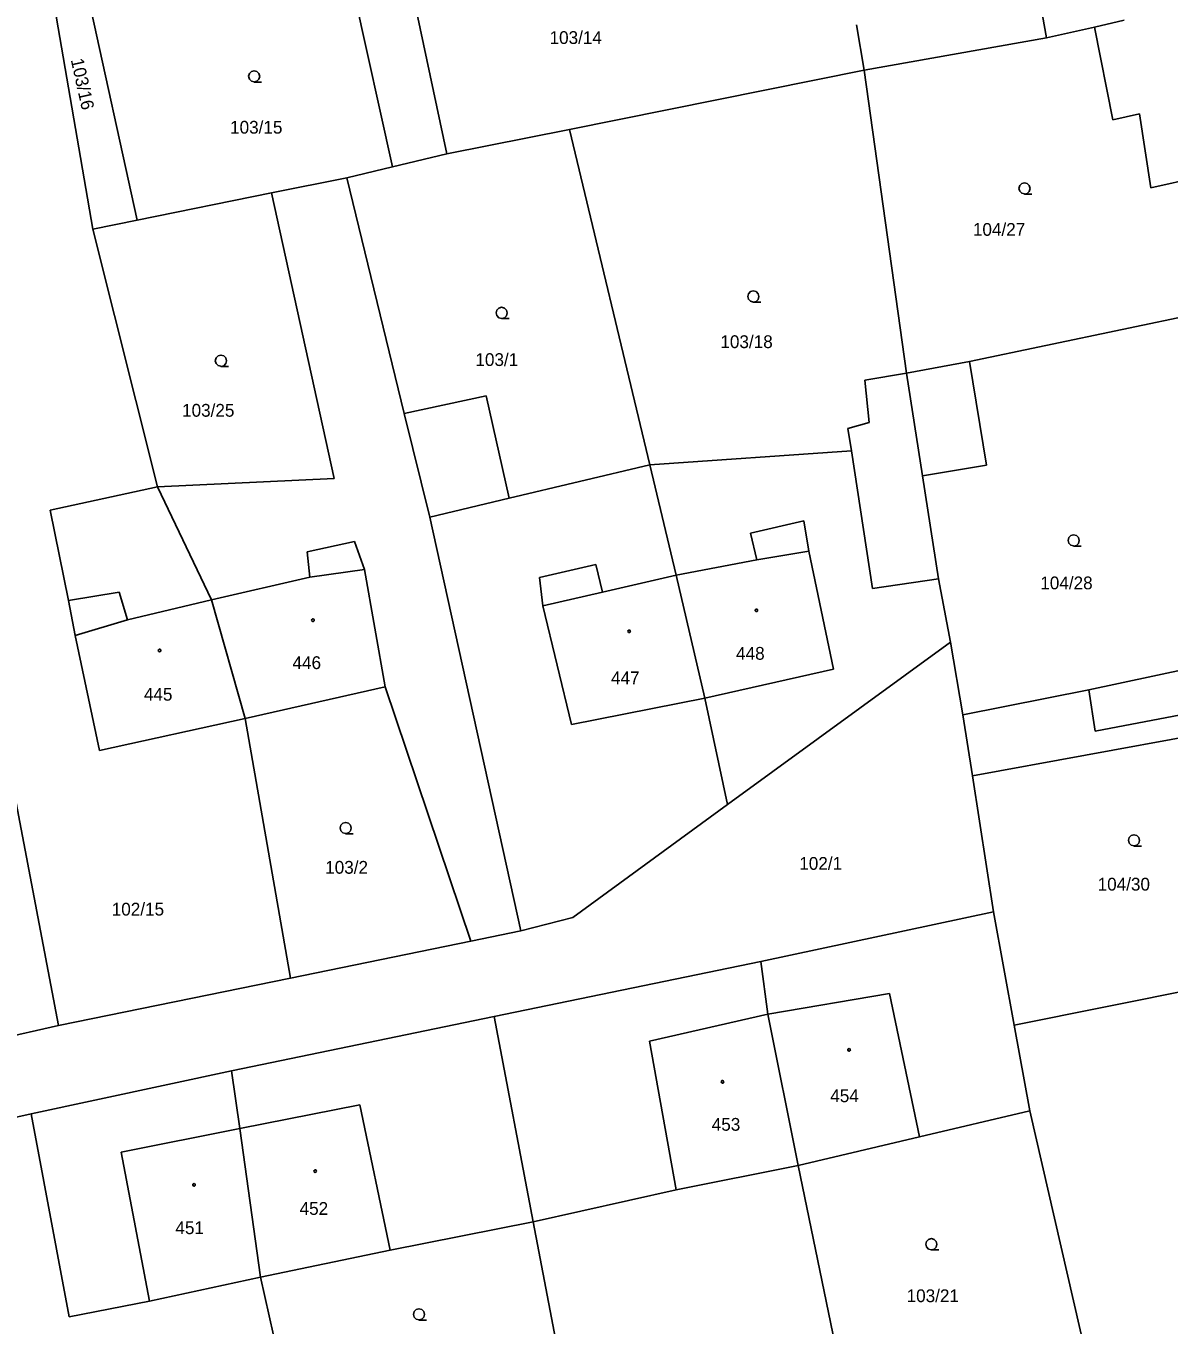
# Model space of a CAD drawing. Extents: x -757994 to -755874, y -1047691 to -1046119.
# Drawn here: x -756795.4 to -756719.4, y -1047241.1 to -1047154.8 of the extents above; entities that cross this region are included whole.
import ezdxf

# ---------------------------------------------------------------- set-up
doc = ezdxf.new("R2010")
doc.units = 0
doc.layers.add('katastrální mapa', color=7, linetype='Continuous')

msp = doc.modelspace()

# ---------------------------------------------------------------- linework, layer by layer
at = {"layer": 'katastrální mapa'}
for p, q in [((-756772.63, -1047138.82), (-756767.41, -1047163.3)), ((-756787.99, -1047167.7), (-756792.24, -1047148.27)), ((-756774.17, -1047149.9), (-756771.02, -1047164.16)), ((-756793.93, -1047150.88), (-756790.93, -1047168.29)), ((-756727.57, -1047155.59), (-756728.16, -1047152.37)), ((-756740.2, -1047154.72), (-756739.68, -1047157.74)), ((-756727.57, -1047155.59), (-756724.39, -1047154.87)), ((-756722.42, -1047154.41), (-756724.39, -1047154.87)), ((-756724.39, -1047154.87), (-756723.16, -1047161.03)), ((-756739.68, -1047157.74), (-756727.57, -1047155.59)), ((-756759.27, -1047161.67), (-756739.68, -1047157.74)), ((-756739.68, -1047157.74), (-756736.87, -1047177.86)), ((-756723.16, -1047161.03), (-756721.39, -1047160.64)), ((-756721.39, -1047160.64), (-756720.64, -1047165.55)), ((-756767.41, -1047163.3), (-756759.27, -1047161.67)), ((-756759.27, -1047161.67), (-756753.93, -1047183.96)), ((-756767.41, -1047163.3), (-756771.02, -1047164.16)), ((-756720.64, -1047165.55), (-756711.7, -1047163.55)), ((-756771.02, -1047164.16), (-756774.06, -1047164.88)), ((-756774.06, -1047164.88), (-756779.07, -1047165.89)), ((-756774.06, -1047164.88), (-756770.25, -1047180.54)), ((-756779.07, -1047165.89), (-756787.99, -1047167.7)), ((-756779.07, -1047165.89), (-756774.89, -1047184.86)), ((-756787.99, -1047167.7), (-756790.93, -1047168.29)), ((-756790.93, -1047168.29), (-756786.63, -1047185.42)), ((-756732.68, -1047177.09), (-756710.05, -1047172.34)), ((-756736.87, -1047177.86), (-756732.68, -1047177.09)), ((-756731.55, -1047183.97), (-756732.68, -1047177.09)), ((-756736.87, -1047177.86), (-756739.64, -1047178.34)), ((-756739.64, -1047178.34), (-756739.36, -1047181.15)), ((-756736.87, -1047177.86), (-756735.82, -1047184.69)), ((-756770.25, -1047180.54), (-756764.81, -1047179.37)), ((-756764.81, -1047179.37), (-756763.28, -1047186.18)), ((-756770.25, -1047180.54), (-756768.55, -1047187.43)), ((-756739.36, -1047181.15), (-756740.77, -1047181.55)), ((-756740.77, -1047181.55), (-756740.54, -1047183.03)), ((-756740.54, -1047183.03), (-756753.93, -1047183.96)), ((-756739.14, -1047192.17), (-756740.54, -1047183.03)), ((-756763.28, -1047186.18), (-756753.93, -1047183.96)), ((-756753.93, -1047183.96), (-756752.17, -1047191.29)), ((-756735.82, -1047184.69), (-756731.55, -1047183.97)), ((-756774.89, -1047184.86), (-756786.63, -1047185.42)), ((-756735.82, -1047184.69), (-756734.76, -1047191.53)), ((-756786.63, -1047185.42), (-756793.76, -1047186.98)), ((-756786.63, -1047185.42), (-756783.04, -1047192.92)), ((-756793.76, -1047186.98), (-756792.56, -1047192.98)), ((-756768.55, -1047187.43), (-756763.28, -1047186.18)), ((-756768.55, -1047187.43), (-756762.5, -1047214.93)), ((-756743.7, -1047187.68), (-756747.25, -1047188.5)), ((-756743.36, -1047189.69), (-756743.7, -1047187.68)), ((-756747.25, -1047188.5), (-756746.82, -1047190.27)), ((-756776.7, -1047189.73), (-756773.56, -1047189.06)), ((-756773.56, -1047189.06), (-756772.89, -1047190.92)), ((-756776.51, -1047191.42), (-756776.7, -1047189.73)), ((-756752.17, -1047191.29), (-756746.82, -1047190.27)), ((-756746.82, -1047190.27), (-756743.36, -1047189.69)), ((-756743.36, -1047189.69), (-756741.73, -1047197.53)), ((-756772.89, -1047190.92), (-756776.51, -1047191.42)), ((-756772.89, -1047190.92), (-756771.51, -1047198.71)), ((-756757.51, -1047190.58), (-756761.26, -1047191.44)), ((-756757.08, -1047192.43), (-756757.51, -1047190.58)), ((-756757.08, -1047192.43), (-756752.17, -1047191.29)), ((-756752.17, -1047191.29), (-756750.27, -1047199.46)), ((-756783.04, -1047192.92), (-756776.51, -1047191.42)), ((-756761.26, -1047191.44), (-756761.03, -1047193.33)), ((-756734.76, -1047191.53), (-756739.14, -1047192.17)), ((-756734.76, -1047191.53), (-756733.96, -1047195.75)), ((-756792.56, -1047192.98), (-756789.19, -1047192.43)), ((-756792.56, -1047192.98), (-756792.11, -1047195.31)), ((-756789.19, -1047192.43), (-756788.64, -1047194.25)), ((-756788.64, -1047194.25), (-756783.04, -1047192.92)), ((-756783.04, -1047192.92), (-756780.81, -1047200.82)), ((-756761.03, -1047193.33), (-756757.08, -1047192.43)), ((-756759.13, -1047201.21), (-756761.03, -1047193.33)), ((-756792.11, -1047195.31), (-756788.64, -1047194.25)), ((-756792.11, -1047195.31), (-756790.48, -1047202.95)), ((-756748.77, -1047206.54), (-756733.96, -1047195.75)), ((-756733.96, -1047195.75), (-756733.13, -1047200.57)), ((-756741.73, -1047197.53), (-756750.27, -1047199.46)), ((-756724.76, -1047198.92), (-756718.23, -1047197.51)), ((-756771.51, -1047198.71), (-756780.81, -1047200.82)), ((-756765.81, -1047215.61), (-756771.51, -1047198.71)), ((-756733.13, -1047200.57), (-756724.76, -1047198.92)), ((-756724.35, -1047201.65), (-756724.76, -1047198.92)), ((-756797.37, -1047199.42), (-756793.22, -1047221.21)), ((-756750.27, -1047199.46), (-756759.13, -1047201.21)), ((-756750.27, -1047199.46), (-756748.77, -1047206.54)), ((-756733.13, -1047200.57), (-756732.5, -1047204.62)), ((-756717.71, -1047200.39), (-756724.35, -1047201.65)), ((-756790.48, -1047202.95), (-756780.81, -1047200.82)), ((-756780.81, -1047200.82), (-756777.8, -1047218.07)), ((-756732.5, -1047204.62), (-756712.12, -1047200.91)), ((-756732.5, -1047204.62), (-756731.09, -1047213.67)), ((-756759.04, -1047214.03), (-756748.77, -1047206.54)), ((-756731.09, -1047213.67), (-756746.55, -1047216.97)), ((-756731.09, -1047213.67), (-756729.73, -1047221.2)), ((-756762.5, -1047214.93), (-756759.04, -1047214.03)), ((-756762.5, -1047214.93), (-756765.81, -1047215.61)), ((-756765.81, -1047215.61), (-756777.8, -1047218.07)), ((-756746.55, -1047216.97), (-756764.26, -1047220.61)), ((-756746.55, -1047216.97), (-756746.08, -1047220.47)), ((-756793.22, -1047221.21), (-756777.8, -1047218.07)), ((-756729.73, -1047221.2), (-756716.41, -1047218.52)), ((-756746.08, -1047220.47), (-756738, -1047219.09)), ((-756738, -1047219.09), (-756736.02, -1047228.62)), ((-756764.26, -1047220.61), (-756781.73, -1047224.23)), ((-756764.26, -1047220.61), (-756761.67, -1047234.27)), ((-756753.94, -1047222.25), (-756746.08, -1047220.47)), ((-756746.08, -1047220.47), (-756744.08, -1047230.52)), ((-756808.23, -1047224.65), (-756793.22, -1047221.21)), ((-756728.69, -1047226.89), (-756729.73, -1047221.2)), ((-756752.17, -1047232.14), (-756753.94, -1047222.25)), ((-756781.73, -1047224.23), (-756795.02, -1047227.09)), ((-756781.73, -1047224.23), (-756781.16, -1047228.07)), ((-756781.16, -1047228.07), (-756773.19, -1047226.48)), ((-756773.19, -1047226.48), (-756771.17, -1047236.14)), ((-756795.02, -1047227.09), (-756799.42, -1047228.04)), ((-756792.51, -1047240.58), (-756795.02, -1047227.09)), ((-756728.69, -1047226.89), (-756736.02, -1047228.62)), ((-756724.6, -1047244.6), (-756728.69, -1047226.89)), ((-756781.16, -1047228.07), (-756789.05, -1047229.64)), ((-756781.16, -1047228.07), (-756779.79, -1047237.94)), ((-756736.02, -1047228.62), (-756744.08, -1047230.52)), ((-756789.05, -1047229.64), (-756787.16, -1047239.54)), ((-756752.17, -1047232.14), (-756744.08, -1047230.52)), ((-756744.08, -1047230.52), (-756739.46, -1047252.9)), ((-756761.67, -1047234.27), (-756752.17, -1047232.14)), ((-756771.17, -1047236.14), (-756761.67, -1047234.27)), ((-756761.67, -1047234.27), (-756759.07, -1047248)), ((-756779.79, -1047237.94), (-756771.17, -1047236.14)), ((-756779.79, -1047237.94), (-756787.16, -1047239.54)), ((-756779.79, -1047237.94), (-756776.67, -1047251.93)), ((-756787.16, -1047239.54), (-756792.51, -1047240.58))]:
    msp.add_line(p, q, dxfattribs=at)
for points in [[(-756780.21, -1047158.51), (-756780.4, -1047158.46), (-756780.535, -1047158.325), (-756780.585, -1047158.14), (-756780.535, -1047157.955), (-756780.4, -1047157.82), (-756780.215, -1047157.77), (-756780.03, -1047157.82), (-756779.895, -1047157.955), (-756779.845, -1047158.145), (-756779.895, -1047158.335), (-756780.03, -1047158.47), (-756780.22, -1047158.52), (-756779.72, -1047158.52)], [(-756729.03, -1047165.96), (-756729.22, -1047165.91), (-756729.355, -1047165.775), (-756729.405, -1047165.59), (-756729.355, -1047165.405), (-756729.22, -1047165.27), (-756729.035, -1047165.22), (-756728.85, -1047165.27), (-756728.715, -1047165.405), (-756728.665, -1047165.595), (-756728.715, -1047165.785), (-756728.85, -1047165.92), (-756729.04, -1047165.97), (-756728.54, -1047165.97)], [(-756747.05, -1047173.14), (-756747.24, -1047173.09), (-756747.375, -1047172.955), (-756747.425, -1047172.77), (-756747.375, -1047172.585), (-756747.24, -1047172.45), (-756747.055, -1047172.4), (-756746.87, -1047172.45), (-756746.735, -1047172.585), (-756746.685, -1047172.775), (-756746.735, -1047172.965), (-756746.87, -1047173.1), (-756747.06, -1047173.15), (-756746.56, -1047173.15)], [(-756763.77, -1047174.23), (-756763.96, -1047174.18), (-756764.095, -1047174.045), (-756764.145, -1047173.86), (-756764.095, -1047173.675), (-756763.96, -1047173.54), (-756763.775, -1047173.49), (-756763.59, -1047173.54), (-756763.455, -1047173.675), (-756763.405, -1047173.865), (-756763.455, -1047174.055), (-756763.59, -1047174.19), (-756763.78, -1047174.24), (-756763.28, -1047174.24)], [(-756782.42, -1047177.41), (-756782.61, -1047177.36), (-756782.745, -1047177.225), (-756782.795, -1047177.04), (-756782.745, -1047176.855), (-756782.61, -1047176.72), (-756782.425, -1047176.67), (-756782.24, -1047176.72), (-756782.105, -1047176.855), (-756782.055, -1047177.045), (-756782.105, -1047177.235), (-756782.24, -1047177.37), (-756782.43, -1047177.42), (-756781.93, -1047177.42)], [(-756725.77, -1047189.35), (-756725.96, -1047189.3), (-756726.095, -1047189.165), (-756726.145, -1047188.98), (-756726.095, -1047188.795), (-756725.96, -1047188.66), (-756725.775, -1047188.61), (-756725.59, -1047188.66), (-756725.455, -1047188.795), (-756725.405, -1047188.985), (-756725.455, -1047189.175), (-756725.59, -1047189.31), (-756725.78, -1047189.36), (-756725.28, -1047189.36)], [(-756774.13, -1047208.46), (-756774.32, -1047208.41), (-756774.455, -1047208.275), (-756774.505, -1047208.09), (-756774.455, -1047207.905), (-756774.32, -1047207.77), (-756774.135, -1047207.72), (-756773.95, -1047207.77), (-756773.815, -1047207.905), (-756773.765, -1047208.095), (-756773.815, -1047208.285), (-756773.95, -1047208.42), (-756774.14, -1047208.47), (-756773.64, -1047208.47)], [(-756721.76, -1047209.28), (-756721.95, -1047209.23), (-756722.085, -1047209.095), (-756722.135, -1047208.91), (-756722.085, -1047208.725), (-756721.95, -1047208.59), (-756721.765, -1047208.54), (-756721.58, -1047208.59), (-756721.445, -1047208.725), (-756721.395, -1047208.915), (-756721.445, -1047209.105), (-756721.58, -1047209.24), (-756721.77, -1047209.29), (-756721.27, -1047209.29)], [(-756735.22, -1047236.12), (-756735.41, -1047236.07), (-756735.545, -1047235.935), (-756735.595, -1047235.75), (-756735.545, -1047235.565), (-756735.41, -1047235.43), (-756735.225, -1047235.38), (-756735.04, -1047235.43), (-756734.905, -1047235.565), (-756734.855, -1047235.755), (-756734.905, -1047235.945), (-756735.04, -1047236.08), (-756735.23, -1047236.13), (-756734.73, -1047236.13)], [(-756769.26, -1047240.78), (-756769.45, -1047240.73), (-756769.585, -1047240.595), (-756769.635, -1047240.41), (-756769.585, -1047240.225), (-756769.45, -1047240.09), (-756769.265, -1047240.04), (-756769.08, -1047240.09), (-756768.945, -1047240.225), (-756768.895, -1047240.415), (-756768.945, -1047240.605), (-756769.08, -1047240.74), (-756769.27, -1047240.79), (-756768.77, -1047240.79)]]:
    msp.add_lwpolyline(points, dxfattribs=at)
for points in [[(-756746.85, -1047193.545), (-756746.8, -1047193.555), (-756746.775, -1047193.6), (-756746.765, -1047193.63), (-756746.775, -1047193.675), (-756746.815, -1047193.71), (-756746.85, -1047193.715), (-756746.895, -1047193.7), (-756746.925, -1047193.67), (-756746.935, -1047193.63), (-756746.925, -1047193.585), (-756746.885, -1047193.55)], [(-756776.31, -1047194.195), (-756776.26, -1047194.205), (-756776.235, -1047194.25), (-756776.225, -1047194.28), (-756776.235, -1047194.325), (-756776.275, -1047194.36), (-756776.31, -1047194.365), (-756776.355, -1047194.35), (-756776.385, -1047194.32), (-756776.395, -1047194.28), (-756776.385, -1047194.235), (-756776.345, -1047194.2)], [(-756755.3, -1047194.935), (-756755.25, -1047194.945), (-756755.225, -1047194.99), (-756755.215, -1047195.02), (-756755.225, -1047195.065), (-756755.265, -1047195.1), (-756755.3, -1047195.105), (-756755.345, -1047195.09), (-756755.375, -1047195.06), (-756755.385, -1047195.02), (-756755.375, -1047194.975), (-756755.335, -1047194.94)], [(-756786.5, -1047196.205), (-756786.45, -1047196.215), (-756786.425, -1047196.26), (-756786.415, -1047196.29), (-756786.425, -1047196.335), (-756786.465, -1047196.37), (-756786.5, -1047196.375), (-756786.545, -1047196.36), (-756786.575, -1047196.33), (-756786.585, -1047196.29), (-756786.575, -1047196.245), (-756786.535, -1047196.21)], [(-756740.69, -1047222.755), (-756740.64, -1047222.765), (-756740.615, -1047222.81), (-756740.605, -1047222.84), (-756740.615, -1047222.885), (-756740.655, -1047222.92), (-756740.69, -1047222.925), (-756740.735, -1047222.91), (-756740.765, -1047222.88), (-756740.775, -1047222.84), (-756740.765, -1047222.795), (-756740.725, -1047222.76)], [(-756749.1, -1047224.875), (-756749.05, -1047224.885), (-756749.025, -1047224.93), (-756749.015, -1047224.96), (-756749.025, -1047225.005), (-756749.065, -1047225.04), (-756749.1, -1047225.045), (-756749.145, -1047225.03), (-756749.175, -1047225), (-756749.185, -1047224.96), (-756749.175, -1047224.915), (-756749.135, -1047224.88)], [(-756776.16, -1047230.805), (-756776.11, -1047230.815), (-756776.085, -1047230.86), (-756776.075, -1047230.89), (-756776.085, -1047230.935), (-756776.125, -1047230.97), (-756776.16, -1047230.975), (-756776.205, -1047230.96), (-756776.235, -1047230.93), (-756776.245, -1047230.89), (-756776.235, -1047230.845), (-756776.195, -1047230.81)], [(-756784.21, -1047231.725), (-756784.16, -1047231.735), (-756784.135, -1047231.78), (-756784.125, -1047231.81), (-756784.135, -1047231.855), (-756784.175, -1047231.89), (-756784.21, -1047231.895), (-756784.255, -1047231.88), (-756784.285, -1047231.85), (-756784.295, -1047231.81), (-756784.285, -1047231.765), (-756784.245, -1047231.73)]]:
    msp.add_lwpolyline(points, close=True, dxfattribs=at)

# ---------------------------------------------------------------- texts
for s, p in [('103/14', (-756760.59, -1047155.99)), ('103/15', (-756781.814, -1047161.95)), ('104/27', (-756732.464, -1047168.74)), ('103/18', (-756749.24, -1047176.2)), ('103/1', (-756765.515, -1047177.39)), ('103/25', (-756785.004, -1047180.76)), ('104/28', (-756727.987, -1047192.23)), ('448', (-756748.197, -1047196.91)), ('446', (-756777.667, -1047197.53)), ('447', (-756756.507, -1047198.54)), ('445', (-756787.541, -1047199.63)), ('103/2', (-756775.496, -1047211.13)), ('102/1', (-756743.999, -1047210.87)), ('104/30', (-756724.177, -1047212.25)), ('102/15', (-756789.677, -1047213.91)), ('454', (-756741.941, -1047226.31)), ('453', (-756749.814, -1047228.21)), ('452', (-756777.197, -1047233.8)), ('451', (-756785.446, -1047235.08)), ('103/21', (-756736.867, -1047239.6))]:
    msp.add_text(s, height=0.85, dxfattribs=at).set_placement(p)
msp.add_text('103/16', height=0.85, rotation=282.52549, dxfattribs=at).set_placement((-756792.404, -1047157.042))

doc.saveas('drawing.dxf')
